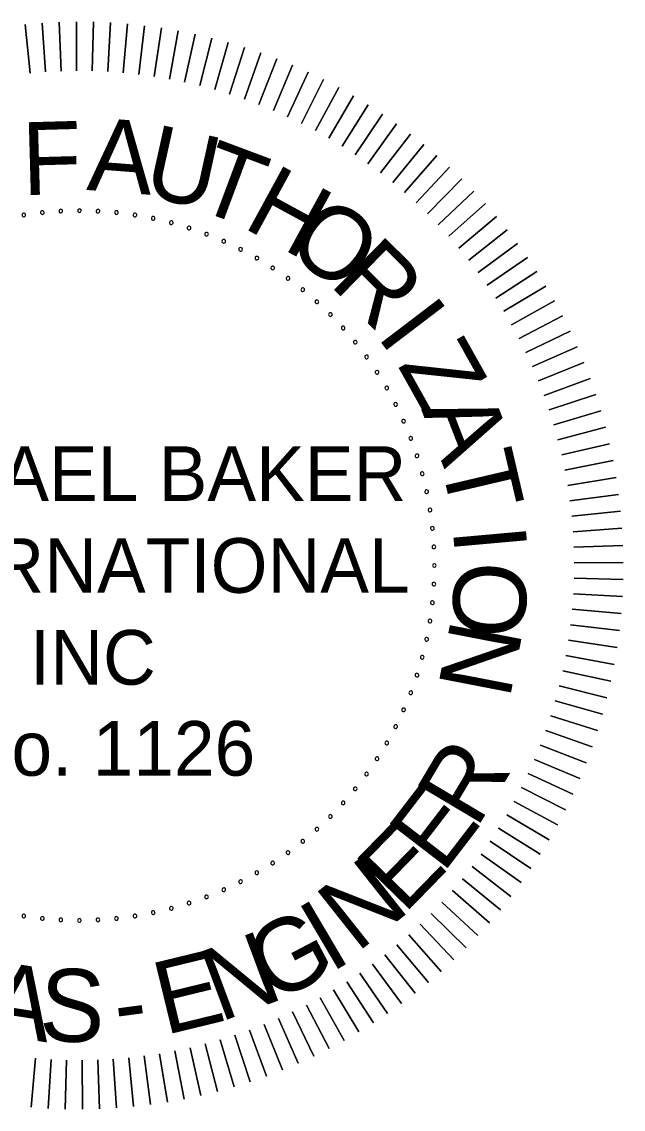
# Model space of a CAD drawing. Extents: x 166 to 3426, y 71 to 2074.
# Drawn here: x 2797 to 2934.6, y 231.2 to 480.1 of the extents above; entities that cross this region are included whole.
import ezdxf

# ---------------------------------------------------------------- set-up
doc = ezdxf.new("R2010")
doc.units = 0
doc.layers.add('G-ANNO-TEXT', color=7, linetype='Continuous')

msp = doc.modelspace()

# ---------------------------------------------------------------- linework, layer by layer
at = {"layer": 'G-ANNO-TEXT'}
for points in [[(2798.9, 468.29), (2797.78, 479.46)], [(2797.78, 479.46), (2798.9, 468.29)], [(2802.45, 468.59), (2801.68, 479.79)], [(2801.68, 479.79), (2802.45, 468.59)], [(2806, 468.78), (2805.58, 480)], [(2805.58, 480), (2806, 468.78)], [(2809.55, 468.86), (2809.49, 480.08)], [(2809.49, 480.08), (2809.55, 468.86)], [(2813.11, 468.82), (2813.4, 480.04)], [(2813.4, 480.04), (2813.11, 468.82)], [(2816.66, 468.67), (2817.31, 479.88)], [(2817.31, 479.88), (2816.66, 468.67)], [(2820.21, 468.41), (2821.21, 479.59)], [(2821.21, 479.59), (2820.21, 468.41)], [(2823.75, 468.04), (2825.09, 479.18)], [(2825.09, 479.18), (2823.75, 468.04)], [(2827.27, 467.56), (2828.97, 478.66)], [(2828.97, 478.66), (2827.27, 467.56)], [(2830.78, 466.97), (2832.82, 478)], [(2832.82, 478), (2830.78, 466.97)], [(2834.27, 466.27), (2836.65, 477.23)], [(2836.65, 477.23), (2834.27, 466.27)], [(2837.73, 465.46), (2840.46, 476.34)], [(2840.46, 476.34), (2837.73, 465.46)], [(2841.17, 464.54), (2844.24, 475.33)], [(2844.24, 475.33), (2841.17, 464.54)], [(2844.57, 463.51), (2847.98, 474.2)], [(2847.98, 474.2), (2844.57, 463.51)], [(2847.94, 462.38), (2851.69, 472.96)], [(2851.69, 472.96), (2847.94, 462.38)], [(2851.28, 461.14), (2855.35, 471.6)], [(2855.35, 471.6), (2851.28, 461.14)], [(2854.57, 459.8), (2858.97, 470.12)], [(2858.97, 470.12), (2854.57, 459.8)], [(2857.82, 458.35), (2862.54, 468.53)], [(2862.54, 468.53), (2857.82, 458.35)], [(2861.02, 456.8), (2866.06, 466.83)], [(2866.06, 466.83), (2861.02, 456.8)], [(2864.18, 455.16), (2869.53, 465.02)], [(2869.53, 465.02), (2864.18, 455.16)], [(2867.27, 453.41), (2872.93, 463.1)], [(2872.93, 463.1), (2867.27, 453.41)], [(2870.32, 451.57), (2876.28, 461.08)], [(2876.28, 461.08), (2870.32, 451.57)], [(2873.3, 449.63), (2879.56, 458.95)], [(2879.56, 458.95), (2873.3, 449.63)], [(2876.22, 447.6), (2882.77, 456.72)], [(2882.77, 456.72), (2876.22, 447.6)], [(2879.08, 445.49), (2885.91, 454.39)], [(2885.91, 454.39), (2879.08, 445.49)], [(2881.87, 443.28), (2888.97, 451.96)], [(2888.97, 451.96), (2881.87, 443.28)], [(2884.58, 440.98), (2891.96, 449.44)], [(2891.96, 449.44), (2884.58, 440.98)], [(2894.86, 446.83), (2887.23, 438.6)], [(2887.23, 438.6), (2894.86, 446.83)], [(2897.69, 444.12), (2889.8, 436.14)], [(2889.8, 436.14), (2897.69, 444.12)], [(2900.42, 441.33), (2892.29, 433.6)], [(2892.29, 433.6), (2900.42, 441.33)], [(2903.07, 438.45), (2894.69, 430.98)], [(2894.69, 430.98), (2903.07, 438.45)], [(2905.63, 435.49), (2897.02, 428.29)], [(2897.02, 428.29), (2905.63, 435.49)], [(2908.09, 432.46), (2899.26, 425.53)], [(2899.26, 425.53), (2908.09, 432.46)], [(2910.45, 429.34), (2901.41, 422.7)], [(2901.41, 422.7), (2910.45, 429.34)], [(2912.72, 426.16), (2903.47, 419.8)], [(2903.47, 419.8), (2912.72, 426.16)], [(2914.88, 422.9), (2905.44, 416.84)], [(2905.44, 416.84), (2914.88, 422.9)], [(2916.94, 419.58), (2907.32, 413.81)], [(2907.32, 413.81), (2916.94, 419.58)], [(2918.9, 416.2), (2909.09, 410.74)], [(2909.09, 410.74), (2918.9, 416.2)], [(2920.75, 412.75), (2910.78, 407.6)], [(2910.78, 407.6), (2920.75, 412.75)], [(2922.49, 409.25), (2912.36, 404.42)], [(2912.36, 404.42), (2922.49, 409.25)], [(2924.12, 405.7), (2913.84, 401.18)], [(2913.84, 401.18), (2924.12, 405.7)], [(2925.63, 402.09), (2915.22, 397.9)], [(2915.22, 397.9), (2925.63, 402.09)], [(2927.03, 398.44), (2916.5, 394.58)], [(2916.5, 394.58), (2927.03, 398.44)], [(2928.32, 394.75), (2917.67, 391.23)], [(2917.67, 391.23), (2928.32, 394.75)], [(2929.49, 391.02), (2918.73, 387.83)], [(2918.73, 387.83), (2929.49, 391.02)], [(2930.54, 387.26), (2919.69, 384.41)], [(2919.69, 384.41), (2930.54, 387.26)], [(2931.48, 383.46), (2920.54, 380.95)], [(2920.54, 380.95), (2931.48, 383.46)], [(2932.29, 379.64), (2921.28, 377.47)], [(2921.28, 377.47), (2932.29, 379.64)], [(2932.98, 375.79), (2921.91, 373.97)], [(2921.91, 373.97), (2932.98, 375.79)], [(2933.56, 371.92), (2922.43, 370.46)], [(2922.43, 370.46), (2933.56, 371.92)], [(2934.01, 368.04), (2922.84, 366.92)], [(2922.84, 366.92), (2934.01, 368.04)], [(2934.34, 364.15), (2923.14, 363.38)], [(2923.14, 363.38), (2934.34, 364.15)], [(2934.54, 360.24), (2923.33, 359.83)], [(2923.33, 359.83), (2934.54, 360.24)], [(2934.63, 356.33), (2923.4, 356.27)], [(2923.4, 356.27), (2934.63, 356.33)], [(2934.59, 352.42), (2923.37, 352.71)], [(2923.37, 352.71), (2934.59, 352.42)], [(2934.42, 348.52), (2923.22, 349.16)], [(2923.22, 349.16), (2934.42, 348.52)], [(2934.14, 344.62), (2922.96, 345.61)], [(2922.96, 345.61), (2934.14, 344.62)], [(2933.73, 340.73), (2922.59, 342.08)], [(2922.59, 342.08), (2933.73, 340.73)], [(2933.2, 336.86), (2922.11, 338.55)], [(2922.11, 338.55), (2933.2, 336.86)], [(2932.55, 333), (2921.52, 335.04)], [(2921.52, 335.04), (2932.55, 333)], [(2931.78, 329.17), (2920.81, 331.56)], [(2920.81, 331.56), (2931.78, 329.17)], [(2930.89, 325.36), (2920, 328.09)], [(2920, 328.09), (2930.89, 325.36)], [(2929.88, 321.59), (2919.08, 324.66)], [(2919.08, 324.66), (2929.88, 321.59)], [(2928.75, 317.85), (2918.06, 321.25)], [(2918.06, 321.25), (2928.75, 317.85)], [(2927.5, 314.14), (2916.92, 317.88)], [(2916.92, 317.88), (2927.5, 314.14)], [(2926.14, 310.48), (2915.68, 314.55)], [(2915.68, 314.55), (2926.14, 310.48)], [(2924.67, 306.86), (2914.34, 311.25)], [(2914.34, 311.25), (2924.67, 306.86)], [(2923.08, 303.28), (2912.9, 308.01)], [(2912.9, 308.01), (2923.08, 303.28)], [(2921.38, 299.76), (2911.35, 304.8)], [(2911.35, 304.8), (2921.38, 299.76)], [(2919.57, 296.3), (2909.7, 301.65)], [(2909.7, 301.65), (2919.57, 296.3)], [(2917.65, 292.89), (2907.96, 298.55)], [(2907.96, 298.55), (2917.65, 292.89)], [(2915.62, 289.55), (2906.12, 295.51)], [(2906.12, 295.51), (2915.62, 289.55)], [(2913.5, 286.27), (2904.18, 292.52)], [(2904.18, 292.52), (2913.5, 286.27)], [(2911.27, 283.06), (2902.15, 289.6)], [(2902.15, 289.6), (2911.27, 283.06)], [(2908.94, 279.92), (2900.03, 286.75)], [(2900.03, 286.75), (2908.94, 279.92)], [(2906.51, 276.85), (2897.82, 283.96)], [(2897.82, 283.96), (2906.51, 276.85)], [(2903.99, 273.87), (2895.53, 281.24)], [(2895.53, 281.24), (2903.99, 273.87)], [(2901.37, 270.96), (2893.15, 278.6)], [(2893.15, 278.6), (2901.37, 270.96)], [(2898.67, 268.14), (2890.69, 276.03)], [(2890.69, 276.03), (2898.67, 268.14)], [(2895.88, 265.4), (2888.15, 273.54)], [(2888.15, 273.54), (2895.88, 265.4)], [(2890.04, 260.2), (2882.84, 268.81)], [(2882.84, 268.81), (2890.04, 260.2)], [(2893, 262.75), (2885.53, 271.13)], [(2885.53, 271.13), (2893, 262.75)], [(2887, 257.74), (2880.08, 266.57)], [(2880.08, 266.57), (2887, 257.74)], [(2883.89, 255.37), (2877.24, 264.42)], [(2877.24, 264.42), (2883.89, 255.37)], [(2880.7, 253.11), (2874.34, 262.35)], [(2874.34, 262.35), (2880.7, 253.11)], [(2877.45, 250.94), (2871.38, 260.39)], [(2871.38, 260.39), (2877.45, 250.94)], [(2870.74, 246.93), (2865.28, 256.73)], [(2865.28, 256.73), (2870.74, 246.93)], [(2874.13, 248.88), (2868.36, 258.51)], [(2868.36, 258.51), (2874.13, 248.88)], [(2867.3, 245.08), (2862.15, 255.05)], [(2862.15, 255.05), (2867.3, 245.08)], [(2860.24, 241.71), (2855.73, 251.98)], [(2855.73, 251.98), (2860.24, 241.71)], [(2863.8, 243.34), (2858.96, 253.47)], [(2858.96, 253.47), (2863.8, 243.34)], [(2852.99, 238.79), (2849.13, 249.33)], [(2849.13, 249.33), (2852.99, 238.79)], [(2856.64, 240.19), (2852.45, 250.61)], [(2852.45, 250.61), (2856.64, 240.19)], [(2845.57, 236.33), (2842.38, 247.09)], [(2842.38, 247.09), (2845.57, 236.33)], [(2849.3, 237.51), (2845.77, 248.16)], [(2845.77, 248.16), (2849.3, 237.51)], [(2830.34, 232.84), (2828.52, 243.92)], [(2828.52, 243.92), (2830.34, 232.84)], [(2834.18, 233.53), (2832.02, 244.55)], [(2832.02, 244.55), (2834.18, 233.53)], [(2838.01, 234.35), (2835.5, 245.29)], [(2835.5, 245.29), (2838.01, 234.35)], [(2841.8, 235.28), (2838.95, 246.14)], [(2838.95, 246.14), (2841.8, 235.28)], [(2799.17, 231.69), (2800.16, 242.87)], [(2800.16, 242.87), (2799.17, 231.69)], [(2803.06, 231.4), (2803.71, 242.61)], [(2803.71, 242.61), (2803.06, 231.4)], [(2806.97, 231.24), (2807.26, 242.46)], [(2807.26, 242.46), (2806.97, 231.24)], [(2810.88, 231.2), (2810.82, 242.42)], [(2810.82, 242.42), (2810.88, 231.2)], [(2814.79, 231.28), (2814.37, 242.5)], [(2814.37, 242.5), (2814.79, 231.28)], [(2818.69, 231.49), (2817.92, 242.69)], [(2817.92, 242.69), (2818.69, 231.49)], [(2822.59, 231.82), (2821.47, 242.98)], [(2821.47, 242.98), (2822.59, 231.82)], [(2826.47, 232.27), (2825, 243.39)], [(2825, 243.39), (2826.47, 232.27)]]:
    msp.add_lwpolyline(points, dxfattribs=at)
for centre, start, end in [((2797.48, 435.85), 9, 189), ((2797.48, 435.85), 189, 9), ((2801.7, 436.41), 6, 186), ((2801.7, 436.41), 186, 6), ((2805.94, 436.74), 3, 183), ((2805.94, 436.74), 183, 3), ((2810.19, 436.85), 0, 180), ((2810.19, 436.85), 180, 0), ((2814.44, 436.74), 357, 177), ((2814.44, 436.74), 177, 357), ((2818.67, 436.41), 354, 174), ((2818.67, 436.41), 174, 354), ((2822.89, 435.85), 171, 351), ((2822.89, 435.85), 351, 171), ((2827.07, 435.08), 168, 348), ((2827.07, 435.08), 348, 168), ((2831.21, 434.09), 165, 345), ((2831.21, 434.09), 345, 165), ((2835.28, 432.88), 342, 162), ((2835.28, 432.88), 162, 342), ((2839.29, 431.46), 159, 339), ((2839.29, 431.46), 339, 159), ((2843.22, 429.83), 156, 336), ((2843.22, 429.83), 336, 156), ((2847.06, 428), 153, 333), ((2847.06, 428), 333, 153), ((2850.79, 425.97), 150, 330), ((2850.79, 425.97), 330, 150), ((2854.42, 423.75), 147, 327), ((2854.42, 423.75), 327, 147), ((2857.92, 421.34), 144, 324), ((2857.92, 421.34), 324, 144), ((2861.3, 418.76), 141, 321), ((2861.3, 418.76), 321, 141), ((2864.53, 415.99), 138, 318), ((2864.53, 415.99), 318, 138), ((2867.61, 413.07), 135, 315), ((2867.61, 413.07), 315, 135), ((2870.54, 409.98), 132, 312), ((2870.54, 409.98), 312, 132), ((2873.3, 406.75), 129, 309), ((2873.3, 406.75), 309, 129), ((2875.89, 403.38), 126, 306), ((2875.89, 403.38), 306, 126), ((2878.3, 399.87), 123, 303), ((2878.3, 399.87), 303, 123), ((2880.52, 396.25), 120, 300), ((2880.52, 396.25), 300, 120), ((2882.55, 392.51), 117, 297), ((2882.55, 392.51), 297, 117), ((2884.38, 388.67), 114, 294), ((2884.38, 388.67), 294, 114), ((2886.01, 384.74), 111, 291), ((2886.01, 384.74), 291, 111), ((2887.43, 380.74), 108, 288), ((2887.43, 380.74), 288, 108), ((2888.63, 376.66), 105, 285), ((2888.63, 376.66), 285, 105), ((2889.63, 372.53), 102, 282), ((2889.63, 372.53), 282, 102), ((2890.4, 368.34), 99, 279), ((2890.4, 368.34), 279, 99), ((2890.96, 364.13), 96, 276), ((2890.96, 364.13), 276, 96), ((2891.29, 359.89), 93, 273), ((2891.29, 359.89), 273, 93), ((2891.4, 355.64), 90, 270), ((2891.4, 355.64), 270, 90), ((2891.29, 351.39), 87, 267), ((2891.29, 351.39), 267, 87), ((2890.96, 347.15), 84, 264), ((2890.96, 347.15), 264, 84), ((2890.4, 342.93), 81, 261), ((2890.4, 342.93), 261, 81), ((2889.63, 338.75), 78, 258), ((2889.63, 338.75), 258, 78), ((2888.63, 334.62), 75, 255), ((2888.63, 334.62), 255, 75), ((2887.43, 330.54), 72, 252), ((2887.43, 330.54), 252, 72), ((2886.01, 326.53), 69, 249), ((2886.01, 326.53), 249, 69), ((2884.38, 322.61), 66, 246), ((2884.38, 322.61), 246, 66), ((2882.55, 318.77), 63, 243), ((2882.55, 318.77), 243, 63), ((2880.52, 315.03), 60, 240), ((2880.52, 315.03), 240, 60), ((2878.3, 311.41), 57, 237), ((2878.3, 311.41), 237, 57), ((2875.89, 307.9), 54, 234), ((2875.89, 307.9), 234, 54), ((2873.3, 304.53), 51, 231), ((2873.3, 304.53), 231, 51), ((2870.54, 301.3), 48, 228), ((2870.54, 301.3), 228, 48), ((2867.61, 298.21), 45, 225), ((2867.61, 298.21), 225, 45), ((2864.53, 295.29), 42, 222), ((2864.53, 295.29), 222, 42), ((2861.3, 292.52), 39, 219), ((2861.3, 292.52), 219, 39), ((2857.92, 289.94), 36, 216), ((2857.92, 289.94), 216, 36), ((2854.42, 287.53), 33, 213), ((2854.42, 287.53), 213, 33), ((2850.79, 285.31), 30, 210), ((2850.79, 285.31), 210, 30), ((2843.22, 281.45), 24, 204), ((2843.22, 281.45), 204, 24), ((2847.06, 283.28), 27, 207), ((2847.06, 283.28), 207, 27), ((2835.28, 278.4), 18, 198), ((2839.29, 279.82), 21, 201), ((2839.29, 279.82), 201, 21), ((2827.07, 276.2), 12, 192), ((2827.07, 276.2), 192, 12), ((2831.21, 277.19), 15, 195), ((2831.21, 277.19), 195, 15), ((2835.28, 278.4), 198, 18), ((2797.48, 275.42), 171, 351), ((2797.48, 275.42), 351, 171), ((2801.7, 274.87), 354, 174), ((2801.7, 274.87), 174, 354), ((2805.94, 274.54), 357, 177), ((2805.94, 274.54), 177, 357), ((2810.19, 274.42), 0, 180), ((2810.19, 274.42), 180, 0), ((2814.44, 274.54), 3, 183), ((2814.44, 274.54), 183, 3), ((2818.67, 274.87), 6, 186), ((2818.67, 274.87), 186, 6), ((2822.89, 275.42), 9, 189), ((2822.89, 275.42), 189, 9)]:
    msp.add_arc(centre, 0.417, start, end, dxfattribs=at)

# ---------------------------------------------------------------- texts
for s, rotation, p in [('F', 1.5867, (2797.25, 440.37)), ('A', 355.5955, (2811.7, 441.6)), ('U', 347.5481, (2824.31, 440.41)), ('T', 339.5007, (2835.95, 437.63)), ('H', 331.4533, (2847.25, 433.17)), ('O', 323.4059, (2856.82, 427.9)), ('R', 315.3585, (2867.15, 420)), ('I', 307.3112, (2877.99, 408.26)), ('Z', 299.2638, (2882.88, 401.47)), ('A', 291.2164, (2888.35, 391.44)), ('T', 283.169, (2892.7, 379.65)), ('I', 275.1216, (2895.59, 364.05)), ('O', 267.0743, (2896.18, 356.89)), ('N', 259.0269, (2895.3, 343.78)), ('R', 59.2262, (2901.05, 295.2)), ('E', 52.4765, (2893.32, 284.94)), ('E', 45.7268, (2884.43, 275.66)), ('N', 38.4196, (2873.66, 266.86)), ('I', 30.5495, (2867.6, 262.27)), ('G', 27.7404, (2854.43, 255.28)), ('N', 20.4332, (2842.29, 251.07)), ('E', 13.6835, (2829.73, 248.13)), ('A', 351.1991, (2788.13, 248.76)), ('S', 357.9489, (2800.85, 246.91)), ('-', 7.5077, (2819.04, 246.87))]:
    msp.add_text(s, height=16.67, rotation=rotation, dxfattribs=at).set_placement(p)
for s, height, p in [('MICHAEL BAKER', 12.5016, (2749.36, 370.42)), (' INTERNATIONAL', 12.5016, (2747.35, 349.39)), ('INC', 12.502, (2798.87, 328.37)), (' No. 1126', 12.502, (2777.92, 307.54))]:
    msp.add_text(s, height=height, dxfattribs=at).set_placement(p)

doc.saveas('drawing.dxf')
